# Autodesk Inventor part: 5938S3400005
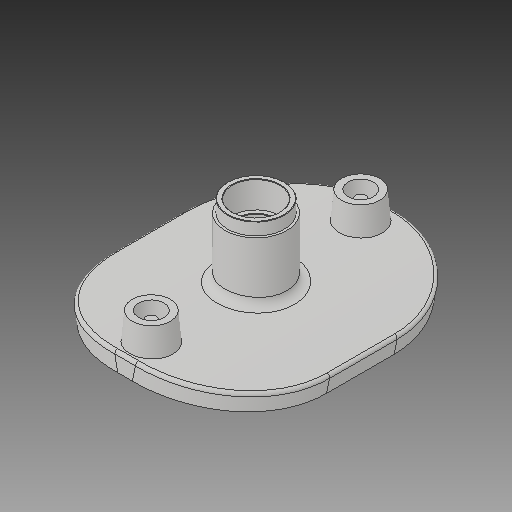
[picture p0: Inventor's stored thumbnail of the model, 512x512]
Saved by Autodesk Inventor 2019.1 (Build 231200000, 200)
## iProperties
Created: 2017-08
Part Number: 5938S3400005
Material: Generic
Description: PLASSON SENSOR ADAPTOR WITH STAINLESS STEEL THREAD 4''16''IPS x 1/2''
Document SubType Name: Modeling
Designer: Кирилл
Density: 1 g/cm^3
Appearance: Default
Author: Кирилл
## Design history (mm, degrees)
derived "5938S.ipt"
feature "Solid1::5938S.ipt"
feature "Solid2::5938S.ipt"
feature "Solid3::5938S.ipt"
tag "TaggingFeature1"
body "Solid1"
other parameters: "d0" = 404.6, "d1" = 84.836, "d3" = 102.87, "d4" = 0, "d5" = 38.1762, "d11" = 262.99, "d38" = 1.2138, "d40" = 219.826, "d41" = 15, "d42" = 41.148, "d46" = 5 deg, "d47" = 4, "d51" = 14, "d52" = 0, "d53" = 3, "d54" = 0, "d75" = 0, "d77" = 0, "d78" = 0.18631, "d82" = 35.052, "d83" = 24.2203, "d84" = 22.3572, "d85" = 14.9048, "d86" = 18.631, "d89" = 10.5156, "d90" = 4.90728, "d95" = 3.175, "d97" = 360 deg, "d99" = 7.0104, "d_" = 404.6, "B_" = 84.836, "H_" = 35.052, "L_" = 102.87, "G_" = 18.631
